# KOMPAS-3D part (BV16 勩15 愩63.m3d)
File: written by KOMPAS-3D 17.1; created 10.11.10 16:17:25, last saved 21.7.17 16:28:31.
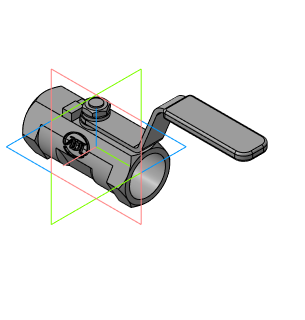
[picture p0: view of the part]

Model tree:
1. Плоскость XY
2. Плоскость ZX
3. Плоскость ZY
4. Ось X
5. Ось Y
6. Ось Z
7. Начало координат
8. Операция без истории:2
